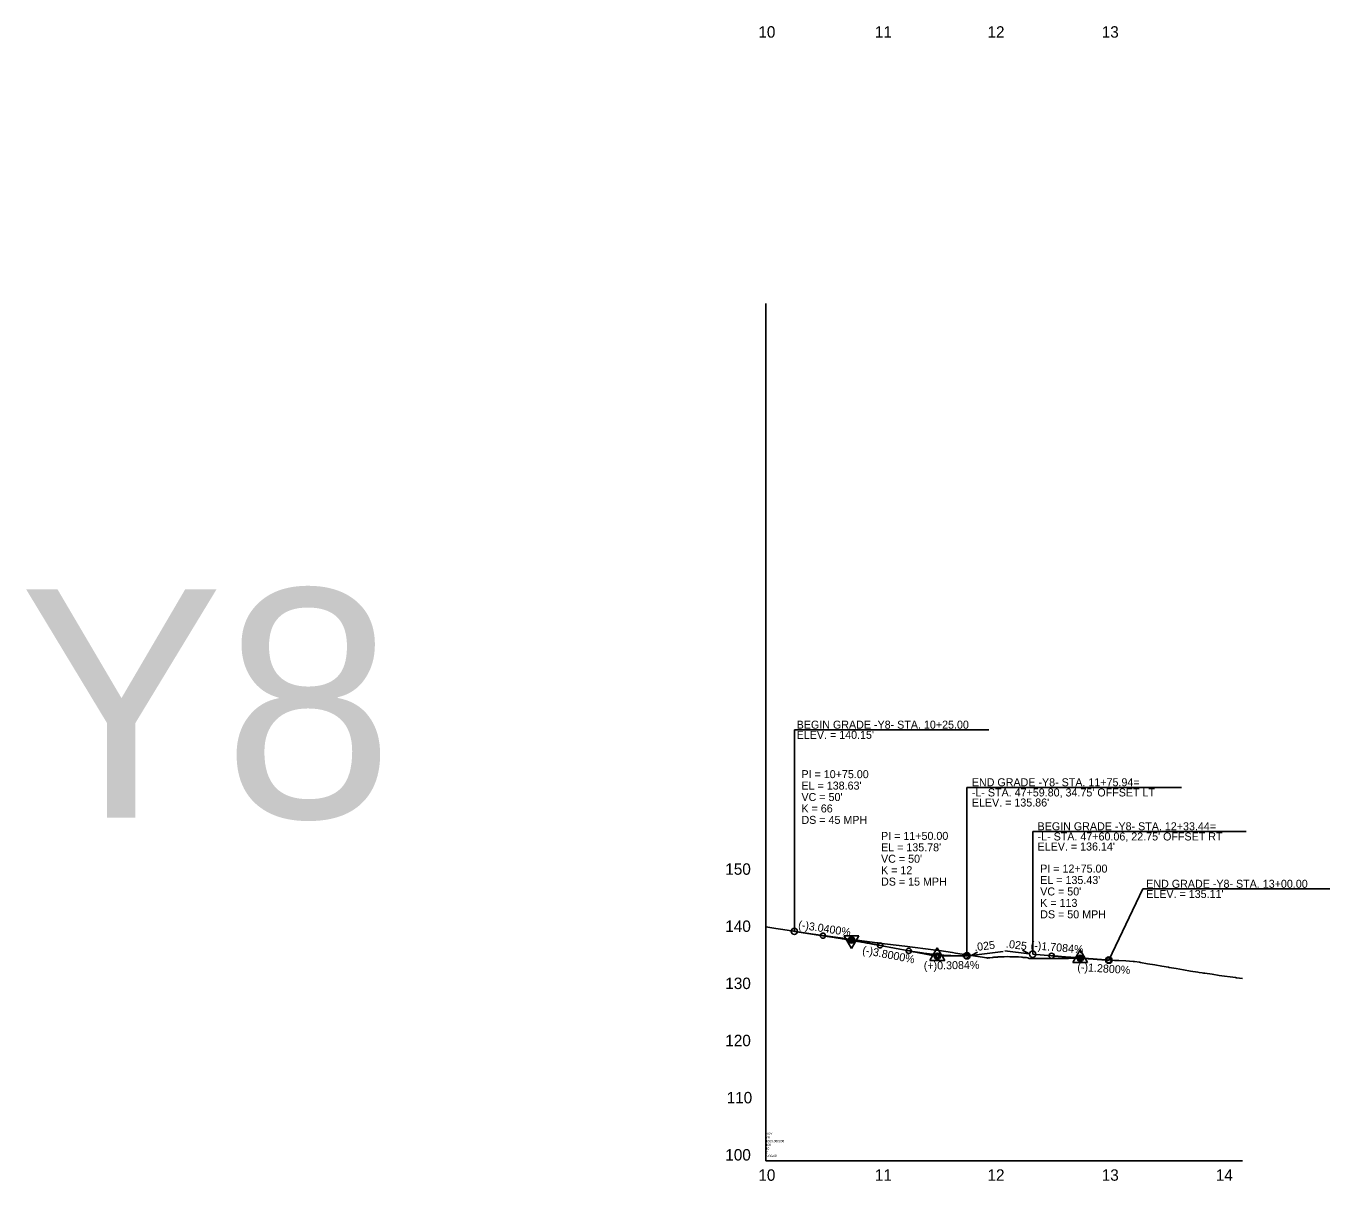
# Model space of a CAD drawing. Extents: x 1778432 to 1784301, y 601022 to 621789.
# Drawn here: x 1779496 to 1780636, y 609022 to 610032 of the extents above; entities that cross this region are included whole.
import ezdxf

# ---------------------------------------------------------------- set-up
doc = ezdxf.new("R2010")
doc.units = 0
for name, color, linetype in [('Exist Profile Cell', 7, 'Continuous'), ('Exist Vertical Profile Ground Line', 7, 'Continuous'), ('Exist Vertical Profile Horizontal Axis Label Major', 7, 'Continuous'), ('Exist Vertical Profile Vertical Axis Label', 7, 'Continuous'), ('Prop PFL Text', 7, 'Continuous'), ('Prop PFL VPI Symbol CELL', 7, 'Continuous'), ('Prop Vertical Profile Curve Label', 7, 'Continuous'), ('Prop Vertical Profile Grade', 7, 'Continuous'), ('Prop Vertical Profile Grade Label', 7, 'Continuous'), ('Prop VPI Label', 7, 'Continuous')]:
    doc.layers.add(name, color=color, linetype=linetype)

msp = doc.modelspace()

# ---------------------------------------------------------------- linework, layer by layer
at = {"layer": 'Exist Profile Cell'}
for q in [(1780143, 609789.2), (1780560, 609039.2), (1780143, 609039.2)]:
    msp.add_line((1780143, 609039.2), q, dxfattribs=at)
at = {"layer": 'Exist Vertical Profile Ground Line'}
msp.add_lwpolyline([(1780143, 609243.7), (1780151.9, 609242.4), (1780155.9, 609241.8), (1780180.6, 609238), (1780181.9, 609237.8), (1780182.3, 609237.8), (1780210.3, 609233.9), (1780211.6, 609233.7), (1780240.4, 609229.8), (1780241.1, 609229.7), (1780242, 609229.6), (1780264.7, 609226.8), (1780291.6, 609223.5), (1780294.5, 609223.2), (1780306.2, 609221.4), (1780309, 609220.9), (1780336.4, 609216.7), (1780336.9, 609216.5), (1780337.6, 609216.6), (1780338.9, 609216.7), (1780341.1, 609217), (1780341.8, 609217.1), (1780342.1, 609217.2), (1780345.1, 609217.4), (1780345.6, 609217.4), (1780346.2, 609217.5), (1780347.4, 609217.7), (1780348.3, 609217.7), (1780349.2, 609217.7), (1780350.4, 609217.7), (1780351, 609217.7), (1780351.4, 609217.7), (1780354.6, 609217.8), (1780356.3, 609217.7), (1780357.7, 609217.6), (1780358.6, 609217.7), (1780360.9, 609217.7), (1780361.6, 609217.7), (1780362.6, 609217.7), (1780363.4, 609217.7), (1780364, 609217.6), (1780366.7, 609217.3), (1780367.2, 609217.3), (1780368.2, 609217), (1780370.6, 609217), (1780370.9, 609216.9), (1780372.3, 609216.8), (1780372.9, 609216.5), (1780373.4, 609216.2), (1780377.9, 609216.1), (1780382.7, 609216.1), (1780389, 609216.2), (1780395.3, 609216.2), (1780401.6, 609216.2), (1780403.3, 609216.2), (1780404.3, 609216.2), (1780407.8, 609216.2), (1780414.1, 609216.3), (1780414.4, 609216.3), (1780419.6, 609216.2), (1780419.9, 609216.2), (1780420.4, 609216.2), (1780426.7, 609215.8), (1780432.9, 609215.4), (1780439.2, 609215), (1780445.5, 609214.6), (1780448.1, 609214.4), (1780451.8, 609214.3), (1780458, 609214), (1780464.3, 609213.6), (1780465.6, 609213.5), (1780469.9, 609212.8), (1780470.6, 609212.7), (1780476.9, 609211.6), (1780483.1, 609210.6), (1780489.4, 609209.5), (1780495.2, 609208.5), (1780495.8, 609208.4), (1780502, 609207.3), (1780508.2, 609206.3), (1780514.5, 609205.2), (1780520.8, 609204.1), (1780521.9, 609203.9), (1780524.7, 609203.5), (1780525.8, 609203.4), (1780527.1, 609203.2), (1780533.3, 609202.3), (1780539.6, 609201.4), (1780553.7, 609199.4), (1780554.7, 609199.3), (1780560, 609198.5)], dxfattribs=at)
at = {"layer": 'Prop PFL VPI Symbol CELL'}
for p, q in [((1780218, 609224.9), (1780211.5, 609236.1)), ((1780224.4, 609236.1), (1780211.5, 609236.1)), ((1780218, 609224.9), (1780224.4, 609236.1)), ((1780293, 609225.6), (1780286.5, 609214.4)), ((1780293, 609225.6), (1780299.5, 609214.4)), ((1780418, 609223.8), (1780411.5, 609212.6)), ((1780418, 609223.8), (1780424.5, 609212.6)), ((1780286.5, 609214.4), (1780299.5, 609214.4)), ((1780411.5, 609212.6), (1780424.5, 609212.6))]:
    msp.add_line(p, q, dxfattribs=at)
for centre, radius in [((1780218, 609232.3), 1.75), ((1780218, 609232.3), 1.2), ((1780293, 609218.1), 1.75), ((1780293, 609218.1), 1.2), ((1780418, 609216.3), 1.75), ((1780418, 609216.3), 1.2)]:
    msp.add_circle(centre, radius, dxfattribs=at)
at = {"layer": 'Prop Vertical Profile Curve Label'}
for centre in [(1780193, 609236.1), (1780243, 609227.6), (1780268, 609222.8), (1780318, 609218.5), (1780393, 609218.5), (1780443, 609214.7)]:
    msp.add_circle(centre, 2.25, dxfattribs=at)
at = {"layer": 'Prop Vertical Profile Grade'}
for p, q in [((1780168, 609239.9), (1780193, 609236.1)), ((1780243, 609227.6), (1780268, 609222.8)), ((1780318, 609218.5), (1780318.9, 609218.5)), ((1780376.4, 609219.9), (1780393, 609218.5))]:
    msp.add_line(p, q, dxfattribs=at)
for points in [[(1780193, 609236.1), (1780194, 609236), (1780195, 609235.8), (1780196, 609235.7), (1780197, 609235.5), (1780198, 609235.4), (1780199, 609235.2), (1780200, 609235.1), (1780201, 609234.9), (1780202, 609234.7), (1780203, 609234.6), (1780204, 609234.4), (1780205, 609234.3), (1780206, 609234.1), (1780207, 609233.9), (1780208, 609233.8), (1780209, 609233.6), (1780210, 609233.4), (1780211, 609233.3), (1780212, 609233.1), (1780213, 609232.9), (1780214, 609232.8), (1780215, 609232.6), (1780216, 609232.4), (1780217, 609232.3), (1780218, 609232.1), (1780219, 609231.9), (1780220, 609231.8), (1780221, 609231.6), (1780222, 609231.4), (1780223, 609231.2), (1780224, 609231.1), (1780225, 609230.9), (1780226, 609230.7), (1780227, 609230.5), (1780228, 609230.4), (1780229, 609230.2), (1780230, 609230), (1780231, 609229.8), (1780232, 609229.6), (1780233, 609229.5), (1780234, 609229.3), (1780235, 609229.1), (1780236, 609228.9), (1780237, 609228.7), (1780238, 609228.5), (1780239, 609228.3), (1780240, 609228.2), (1780241, 609228), (1780242, 609227.8), (1780243, 609227.6)], [(1780268, 609222.8), (1780269, 609222.7), (1780270, 609222.5), (1780271, 609222.3), (1780272, 609222.1), (1780273, 609222), (1780274, 609221.8), (1780275, 609221.6), (1780276, 609221.5), (1780277, 609221.3), (1780278, 609221.2), (1780279, 609221), (1780280, 609220.9), (1780281, 609220.7), (1780282, 609220.6), (1780283, 609220.5), (1780284, 609220.3), (1780285, 609220.2), (1780286, 609220.1), (1780287, 609220), (1780288, 609219.9), (1780289, 609219.8), (1780290, 609219.7), (1780291, 609219.6), (1780292, 609219.5), (1780293, 609219.4), (1780294, 609219.3), (1780295, 609219.2), (1780296, 609219.1), (1780297, 609219.1), (1780298, 609219), (1780299, 609218.9), (1780300, 609218.9), (1780301, 609218.8), (1780302, 609218.8), (1780303, 609218.7), (1780304, 609218.7), (1780305, 609218.6), (1780306, 609218.6), (1780307, 609218.6), (1780308, 609218.5), (1780309, 609218.5), (1780310, 609218.5), (1780311, 609218.5), (1780312, 609218.5), (1780313, 609218.5), (1780314, 609218.5), (1780315, 609218.5), (1780316, 609218.5), (1780317, 609218.5), (1780318, 609218.5)], [(1780393, 609218.5), (1780394, 609218.4), (1780395, 609218.3), (1780396, 609218.2), (1780397, 609218.1), (1780398, 609218.1), (1780399, 609218), (1780400, 609217.9), (1780401, 609217.8), (1780402, 609217.7), (1780403, 609217.6), (1780404, 609217.6), (1780405, 609217.5), (1780406, 609217.4), (1780407, 609217.3), (1780408, 609217.2), (1780409, 609217.2), (1780410, 609217.1), (1780411, 609217), (1780412, 609216.9), (1780413, 609216.9), (1780414, 609216.8), (1780415, 609216.7), (1780416, 609216.6), (1780417, 609216.5), (1780418, 609216.5), (1780419, 609216.4), (1780420, 609216.3), (1780421, 609216.3), (1780422, 609216.2), (1780423, 609216.1), (1780424, 609216), (1780425, 609216), (1780426, 609215.9), (1780427, 609215.8), (1780428, 609215.7), (1780429, 609215.7), (1780430, 609215.6), (1780431, 609215.5), (1780432, 609215.5), (1780433, 609215.4), (1780434, 609215.3), (1780435, 609215.3), (1780436, 609215.2), (1780437, 609215.1), (1780438, 609215.1), (1780439, 609215), (1780440, 609214.9), (1780441, 609214.9), (1780442, 609214.8), (1780443, 609214.7)]]:
    msp.add_spline(points, degree=3, dxfattribs=at)
at = {"layer": 'Prop VPI Label'}
for p, q in [((1780168, 609239.9), (1780168, 609416.2)), ((1780168, 609416.2), (1780338.1, 609416.2)), ((1780318.9, 609218.5), (1780318.9, 609365.7)), ((1780318.9, 609365.7), (1780506.5, 609365.7)), ((1780376.4, 609219.9), (1780376.4, 609327.2)), ((1780376.4, 609327.2), (1780563, 609327.2)), ((1780443, 609214.7), (1780472.7, 609277)), ((1780472.7, 609277), (1780636.4, 609277)), ((1780193, 609236.1), (1780215.2, 609232.8)), ((1780243, 609227.6), (1780220.7, 609231.8)), ((1780268, 609222.8), (1780290.3, 609218.6)), ((1780322.5, 609218.7), (1780350.5, 609222.2)), ((1780322.5, 609218.7), (1780328.2, 609221.8)), ((1780373.2, 609220.2), (1780352, 609222.9)), ((1780373.2, 609220.2), (1780367.5, 609223.4)), ((1780318, 609218.5), (1780295.7, 609218.1)), ((1780393, 609218.5), (1780415.2, 609216.6)), ((1780443, 609214.7), (1780420.7, 609216.2))]:
    msp.add_line(p, q, dxfattribs=at)
for centre in [(1780168, 609239.9), (1780218, 609232.3), (1780318.9, 609218.5), (1780376.4, 609219.9), (1780293, 609218.1), (1780418, 609216.3), (1780443, 609214.7)]:
    msp.add_circle(centre, 2.75, dxfattribs=at)

# ---------------------------------------------------------------- texts
at = {"layer": 'Exist Profile Cell'}
for s, p in [('RDY', (1780143, 609061.9)), ('Y8', (1780143, 609058.7)), ('1000.000000', (1780143, 609055.4)), ('100', (1780143, 609052.2)), ('10', (1780143, 609048.9)), ('2', (1780143, 609045.7)), ('NOGAP', (1780143, 609042.4))]:
    msp.add_text(s, height=2, dxfattribs=at).set_placement(p)
at = {"layer": 'Exist Vertical Profile Horizontal Axis Label Major'}
for s, p in [('10', (1780136.5, 610021.7)), ('11', (1780238.4, 610021.7)), ('12', (1780336.9, 610021.7)), ('13', (1780436.8, 610021.7)), ('10', (1780136.5, 609021.7)), ('11', (1780238.4, 609021.7)), ('12', (1780336.9, 609021.7)), ('13', (1780436.8, 609021.7)), ('14', (1780536.6, 609021.7))]:
    msp.add_text(s, height=10, dxfattribs=at).set_placement(p)
at = {"layer": 'Exist Vertical Profile Vertical Axis Label'}
for s, p in [('150', (1780107.6, 609289.4)), ('140', (1780107.6, 609239.4)), ('130', (1780107.6, 609189.4)), ('120', (1780107.6, 609139.4)), ('110', (1780108.8, 609089.4)), ('100', (1780107.6, 609039.4))]:
    msp.add_text(s, height=10, dxfattribs=at).set_placement(p)
at = {"layer": 'Prop PFL Text'}
msp.add_text('Y8', height=200, dxfattribs=at).set_placement((1779490.2, 609339.2))
at = {"layer": 'Prop Vertical Profile Curve Label'}
for s, p in [("VC = 50'", (1780174.2, 609353.9)), ('K = 66', (1780174.2, 609343.9)), ('DS = 45 MPH', (1780174.2, 609333.9)), ("VC = 50'", (1780243.8, 609299.9)), ('K = 12', (1780243.8, 609289.9)), ('DS = 15 MPH', (1780243.8, 609279.9)), ("VC = 50'", (1780383, 609271.3)), ('K = 113', (1780383, 609261.3)), ('DS = 50 MPH', (1780383, 609251.3))]:
    msp.add_text(s, height=7, dxfattribs=at).set_placement(p)
at = {"layer": 'Prop Vertical Profile Grade Label'}
for s, rotation, p in [('(-)3.0400%', 351.3634, (1780171, 609242.5)), ('(-)3.8000%', 349.2501, (1780227, 609220.4)), ('.025', 7.125, (1780325.7, 609222.5)), ('.025', 352.875, (1780352.8, 609225.7)), ('(-)1.7084%', 355.1083, (1780374.4, 609224.4)), ('(+)0.3084%', 0.8594, (1780281.2, 609206.4)), ('(-)1.2800%', 356.3675, (1780415.3, 609205.4))]:
    msp.add_text(s, height=7, rotation=rotation, dxfattribs=at).set_placement(p)
at = {"layer": 'Prop VPI Label'}
for s, p in [('BEGIN GRADE -Y8- STA. 10+25.00', (1780170, 609417.2)), ("ELEV. = 140.15'", (1780170, 609408.3)), ('PI = 10+75.00', (1780174.2, 609373.9)), ("EL = 138.63'", (1780174.2, 609363.9)), ('END GRADE -Y8- STA. 11+75.94=', (1780323.2, 609366.8)), ("-L- STA. 47+59.80, 34.75' OFFSET LT", (1780323.2, 609357.9)), ("ELEV. = 135.86'", (1780323.2, 609349.1)), ('BEGIN GRADE -Y8- STA. 12+33.44=', (1780380.7, 609328.3)), ('PI = 11+50.00', (1780243.8, 609319.9)), ("-L- STA. 47+60.06, 22.75' OFFSET RT", (1780380.7, 609319.4)), ("EL = 135.78'", (1780243.8, 609309.9)), ("ELEV. = 136.14'", (1780380.7, 609310.6)), ('PI = 12+75.00', (1780383, 609291.3)), ("EL = 135.43'", (1780383, 609281.3)), ('END GRADE -Y8- STA. 13+00.00', (1780475.7, 609278)), ("ELEV. = 135.11'", (1780475.7, 609269.1))]:
    msp.add_text(s, height=7, dxfattribs=at).set_placement(p)

doc.saveas('drawing.dxf')
